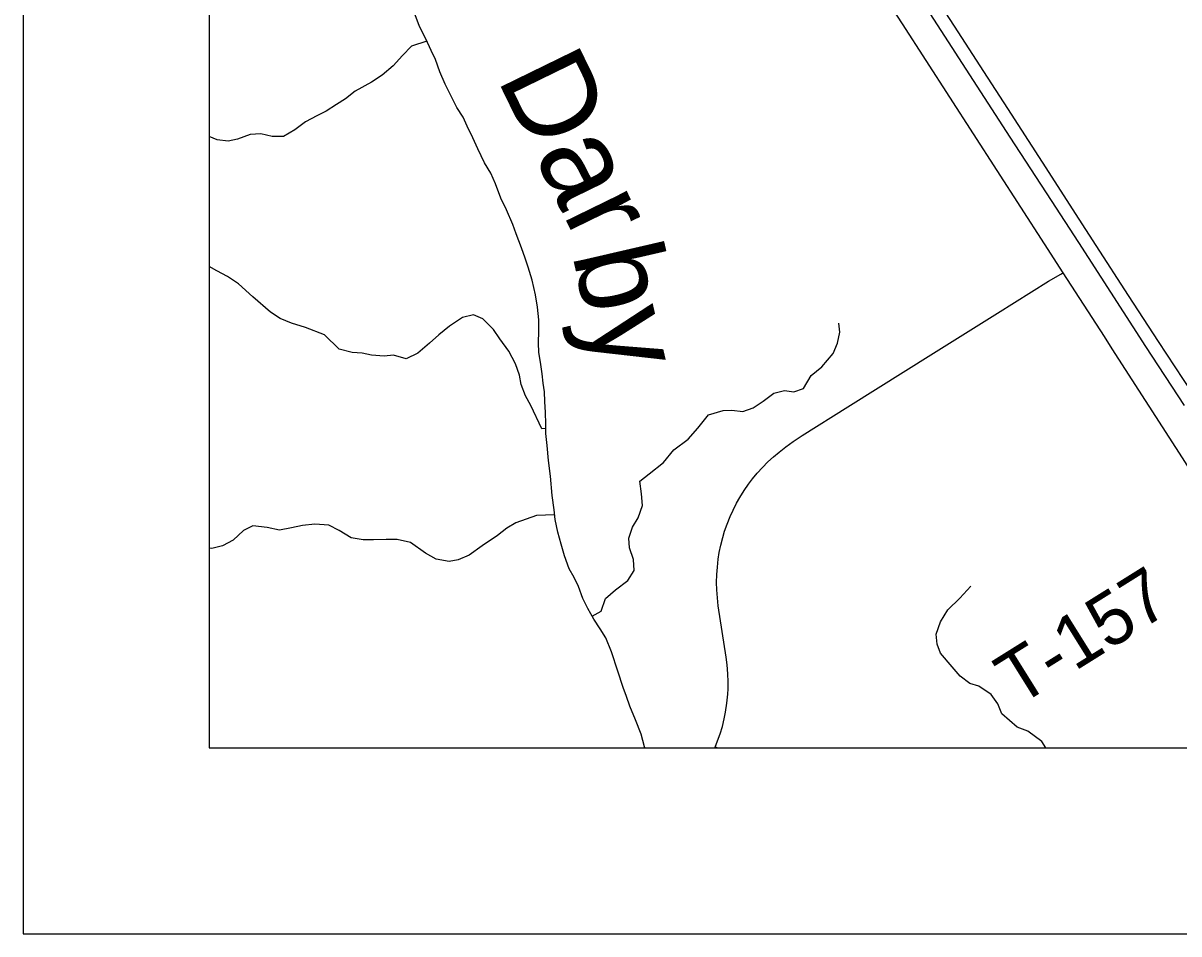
# Model space of a CAD drawing. Extents: x 0 to 34, y 0 to 22.
# Drawn here: x 2 to 2.622, y 14 to 14.49 of the extents above; entities that cross this region are included whole.
import ezdxf

# ---------------------------------------------------------------- set-up
doc = ezdxf.new("R2010")
doc.units = 0
for name, color, linetype in [('GM_X_Corporation', 7, 'Continuous'), ('GM_X_Minor_River', 7, 'Continuous'), ('GM_X_Minor_River_Text', 7, 'Continuous'), ('GM_X_State_Route', 7, 'Continuous'), ('GM_X_Township_Road', 7, 'Continuous'), ('GM_X_Township_Road_Text', 7, 'Continuous'), ('GM_X_US_Route', 7, 'Continuous'), ('SH_Data', 7, 'Continuous')]:
    doc.layers.add(name, color=color, linetype=linetype)

msp = doc.modelspace()

# ---------------------------------------------------------------- linework, layer by layer
at = {"layer": 'GM_X_Corporation'}
msp.add_lwpolyline([(2.1, 20.9), (2.1, 14.1), (2.70517, 14.1), (2.70761, 14.12453), (2.70949, 14.14572), (2.71149, 14.17029), (2.71244, 14.18008), (2.71408, 14.19146), (2.74262, 14.48729), (2.76121, 14.68204), (2.78252, 14.90567), (2.79096, 14.99744), (2.84444, 15.57923), (2.89388, 16.10066)], dxfattribs=at)
msp.add_lwpolyline([(2.1, 15.03648), (2.1, 14.1), (2.70517, 14.1), (2.70761, 14.12453), (2.70949, 14.14572), (2.71149, 14.17029), (2.71244, 14.18008), (2.71408, 14.19146), (2.74262, 14.48729), (2.76121, 14.68204), (2.78252, 14.90567), (2.79096, 14.99744), (2.14799, 15.03391), (2.14359, 15.03416), (2.13937, 15.03437), (2.12058, 15.03531), (2.12001, 15.03535)], close=True, dxfattribs=at)
at = {"layer": 'GM_X_Minor_River'}
for points in [[(2.27008, 14.36335), (2.26808, 14.36888), (2.26516, 14.37652), (2.26334, 14.38148), (2.26004, 14.38931), (2.2569, 14.39562), (2.25418, 14.40344), (2.25161, 14.40917), (2.24827, 14.41472), (2.24459, 14.42218), (2.24183, 14.4281), (2.23889, 14.43441), (2.23668, 14.43919), (2.23334, 14.44436), (2.2302, 14.45048), (2.22708, 14.45698), (2.22414, 14.46367), (2.22177, 14.47016), (2.21957, 14.47512), (2.21662, 14.48143), (2.2133, 14.48793), (2.21038, 14.49576)], [(2.21721, 14.48017), (2.20896, 14.47737), (2.20413, 14.47232), (2.19911, 14.46689), (2.19314, 14.46186), (2.18738, 14.45796), (2.17856, 14.45317), (2.17337, 14.44907), (2.16857, 14.44611), (2.16301, 14.4424), (2.15803, 14.44), (2.1519, 14.43668), (2.14613, 14.43241), (2.14, 14.42889), (2.13391, 14.4288), (2.12786, 14.43022), (2.12215, 14.42992), (2.11527, 14.42737), (2.11032, 14.42631), (2.10444, 14.42697), (2.1, 14.42886)], [(2.33435, 14.1), (2.3342, 14.10054), (2.33241, 14.1074), (2.32949, 14.11503), (2.32637, 14.12248), (2.32455, 14.12763), (2.32273, 14.13259), (2.31983, 14.14136), (2.31657, 14.15166), (2.31346, 14.15929), (2.31049, 14.16408), (2.30696, 14.16926), (2.30382, 14.175), (2.30106, 14.18035), (2.29869, 14.18684), (2.29648, 14.19162), (2.29371, 14.1964), (2.29115, 14.20327), (2.28935, 14.20956), (2.28755, 14.21604), (2.28614, 14.22289), (2.28565, 14.22802), (2.28463, 14.23581), (2.28365, 14.24607), (2.28264, 14.25463), (2.28182, 14.26261), (2.28116, 14.26907), (2.28124, 14.27438), (2.28096, 14.28046), (2.28067, 14.28634), (2.28037, 14.29147), (2.27968, 14.29623), (2.27919, 14.30117), (2.27833, 14.30744), (2.27747, 14.31258), (2.27717, 14.31789), (2.27746, 14.32415), (2.27736, 14.33022), (2.27671, 14.33706), (2.27567, 14.34372), (2.27389, 14.35153), (2.27172, 14.35858), (2.27008, 14.36335)], [(2.2812, 14.27173), (2.27911, 14.27157), (2.27303, 14.28418), (2.27026, 14.28935), (2.26789, 14.29546), (2.26702, 14.3004), (2.26483, 14.30651), (2.26133, 14.31339), (2.25649, 14.3201), (2.25296, 14.32509), (2.24735, 14.33068), (2.24225, 14.33284), (2.23634, 14.33142), (2.22942, 14.32678), (2.22365, 14.32212), (2.21864, 14.31764), (2.21229, 14.31224), (2.20597, 14.3093), (2.19916, 14.3113), (2.19421, 14.31061), (2.18738, 14.31129), (2.18246, 14.31231), (2.17695, 14.31258), (2.16995, 14.3144), (2.16209, 14.32211), (2.15189, 14.32606), (2.14433, 14.32845), (2.13829, 14.33101), (2.13302, 14.33431), (2.12365, 14.34261), (2.11578, 14.34956), (2.10995, 14.35345), (2.10429, 14.35657), (2.1, 14.35895)], [(2.30609, 14.17086), (2.31102, 14.17356), (2.31322, 14.18036), (2.31861, 14.18502), (2.32534, 14.19004), (2.32865, 14.19549), (2.32836, 14.20138), (2.32618, 14.20767), (2.32588, 14.2128), (2.32787, 14.21865), (2.3308, 14.22373), (2.33319, 14.23033), (2.33271, 14.2366), (2.33168, 14.24345), (2.33668, 14.24736), (2.34438, 14.2535), (2.34999, 14.26025), (2.35768, 14.26601), (2.36291, 14.272), (2.36872, 14.27912), (2.37655, 14.28147), (2.3813, 14.28159), (2.38718, 14.28093), (2.39272, 14.28293), (2.3981, 14.28645), (2.40386, 14.29073), (2.40959, 14.29216), (2.41452, 14.29152), (2.41986, 14.29333), (2.42396, 14.30029), (2.42955, 14.30495), (2.43574, 14.31206), (2.43811, 14.31772), (2.43934, 14.32358), (2.43884, 14.32852)], [(2.2859, 14.22541), (2.2761, 14.22494), (2.26502, 14.22112), (2.26022, 14.21816), (2.25522, 14.21425), (2.24697, 14.20868), (2.23986, 14.20367), (2.23393, 14.2011), (2.22916, 14.20022), (2.22215, 14.20147), (2.2165, 14.20478), (2.20842, 14.2104), (2.20123, 14.21203), (2.19534, 14.21212), (2.18849, 14.21184), (2.18299, 14.21193), (2.17654, 14.21297), (2.16995, 14.21687), (2.16449, 14.2198), (2.1569, 14.22029), (2.15023, 14.21963), (2.14433, 14.21839), (2.13785, 14.21716), (2.13122, 14.21859), (2.12363, 14.21947), (2.11846, 14.21689), (2.11306, 14.21166), (2.10731, 14.20871), (2.10159, 14.20728), (2.1, 14.20736)], [(2.55009, 14.1), (2.54801, 14.10354), (2.5405, 14.10897), (2.53464, 14.11115), (2.52639, 14.11829), (2.52439, 14.12364), (2.52067, 14.12882), (2.51409, 14.13328), (2.50917, 14.13468), (2.5041, 14.13856), (2.4998, 14.14355), (2.49346, 14.15105), (2.49163, 14.15582), (2.49115, 14.16114), (2.49353, 14.16775), (2.49743, 14.17433), (2.5038, 14.18049), (2.50979, 14.18704)]]:
    msp.add_lwpolyline(points, dxfattribs=at)
at = {"layer": 'GM_X_State_Route'}
msp.add_lwpolyline([(2.35052, 14.67799), (2.40066, 14.60059), (2.47292, 14.48933), (2.54926, 14.37109), (2.55934, 14.35546), (2.58143, 14.3212), (2.58566, 14.31471), (2.62352, 14.25595), (2.63286, 14.24132), (2.67118, 14.18133), (2.70773, 14.12426)], dxfattribs=at)
at = {"layer": 'GM_X_Township_Road'}
for points in [[(2.37211, 14.1), (2.37239, 14.10061), (2.37251, 14.10087), (2.37494, 14.10754), (2.37621, 14.11158), (2.37707, 14.1156), (2.37781, 14.11929), (2.37856, 14.12412), (2.37904, 14.12891), (2.37917, 14.13181), (2.37922, 14.13556), (2.37906, 14.13984), (2.37872, 14.14475), (2.37817, 14.14876), (2.37387, 14.17639), (2.3731, 14.18509), (2.37297, 14.18889), (2.37312, 14.19321), (2.37346, 14.19722), (2.37389, 14.2016), (2.37438, 14.20505), (2.37523, 14.20898), (2.37635, 14.21325), (2.37735, 14.21649), (2.37876, 14.2204), (2.38031, 14.22438), (2.3819, 14.2278), (2.3838, 14.23171), (2.38553, 14.23464), (2.38778, 14.23844), (2.39021, 14.24186), (2.39236, 14.24476), (2.3949, 14.24778), (2.39771, 14.25087), (2.40063, 14.25383), (2.40356, 14.25649), (2.40673, 14.25907), (2.41035, 14.26199), (2.41419, 14.26481), (2.41906, 14.26802), (2.44354, 14.28339), (2.48963, 14.31224), (2.52417, 14.33377), (2.55151, 14.35099), (2.55821, 14.35482), (2.55934, 14.35546)], [(2.37239, 14.10061), (2.37355, 14.10013), (2.37386, 14.1)]]:
    msp.add_lwpolyline(points, dxfattribs=at)
at = {"layer": 'GM_X_US_Route'}
for points in [[(2.17738, 14.97433), (2.18977, 14.95534), (2.21605, 14.91461), (2.23773, 14.88127), (2.2581, 14.84968), (2.27802, 14.8189), (2.29392, 14.7944), (2.3723, 14.67342), (2.39327, 14.6411), (2.42226, 14.59621), (2.43664, 14.57406), (2.45755, 14.5417), (2.47193, 14.51955), (2.5308, 14.42849), (2.55293, 14.39434), (2.56777, 14.37175), (2.58489, 14.34507), (2.60379, 14.31586), (2.62451, 14.28413)], [(2.48542, 14.51202), (2.50083, 14.48819), (2.51657, 14.46378), (2.52945, 14.4438), (2.54811, 14.415), (2.56796, 14.38435), (2.57707, 14.37026), (2.59438, 14.34334), (2.61056, 14.31865), (2.6285, 14.29141)]]:
    msp.add_lwpolyline(points, dxfattribs=at)
at = {"layer": 'SH_Data'}
for p, q in [((2, 21), (2, 14)), ((2.1, 20.9), (2.1, 14.1)), ((2.1, 14.1), (8.9, 14.1)), ((2, 14), (9, 14))]:
    msp.add_line(p, q, dxfattribs=at)

# ---------------------------------------------------------------- texts
at = {"layer": 'GM_X_Minor_River_Text'}
for s, height, rotation, p in [('Dar', 0.047344, 296.02506, (2.25462, 14.46022)), ('by', 0.047345, 283.02241, (2.29522, 14.36553))]:
    msp.add_text(s, height=height, rotation=rotation, dxfattribs=at).set_placement(p)
at = {"layer": 'GM_X_Township_Road_Text'}
msp.add_text('T-157', height=0.028409, rotation=31.97596, dxfattribs=at).set_placement((2.53519, 14.12202))

doc.saveas('drawing.dxf')
